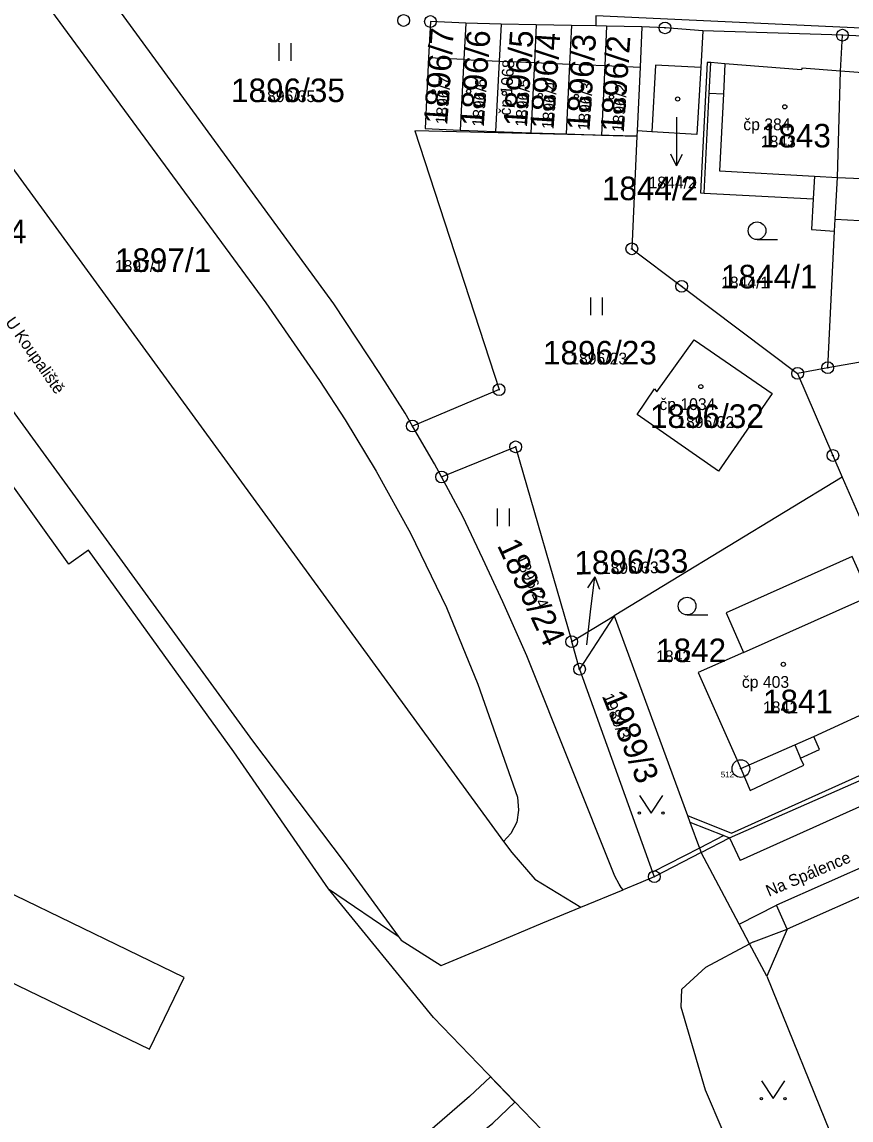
# Model space of a CAD drawing. Extents: x -763628 to -761565, y -976033 to -973833.
# Drawn here: x -762756 to -762685.6, y -975140.5 to -975047.2 of the extents above; entities that cross this region are included whole.
import ezdxf

# ---------------------------------------------------------------- set-up
doc = ezdxf.new("R2010")
doc.units = 0
for name, color, linetype in [('KN_cisla parcel 1000', 7, 'Continuous'), ('KN_cisla parcel 500', 7, 'Continuous'), ('KN_cisla parcel znacky', 7, 'Continuous'), ('KN_cisla popisna 500', 7, 'Continuous'), ('KN_hranice parcel', 7, 'Continuous'), ('KN_popisy', 7, 'Continuous'), ('KN_vecna bremena', 7, 'Continuous'), ('KN_vnitrni kresba parcel', 7, 'Continuous'), ('KN_znacky bodu BP', 7, 'Continuous'), ('KN_znacky budov', 7, 'Continuous'), ('KN_znacky kultur', 7, 'Continuous')]:
    doc.layers.add(name, color=color, linetype=linetype)

msp = doc.modelspace()

# ---------------------------------------------------------------- linework, layer by layer
at = {"layer": 'KN_cisla parcel znacky'}
for p, q in [((-762700.39, -975055.31), (-762700.39, -975056.44)), ((-762700.39, -975056.44), (-762700.39, -975059.441)), ((-762700.39, -975059.441), (-762700.891, -975058.44)), ((-762700.39, -975059.441), (-762699.889, -975058.44)), ((-762707.324, -975094.351), (-762707.943, -975095.284)), ((-762707.69, -975097.33), (-762707.324, -975094.351)), ((-762707.324, -975094.351), (-762706.949, -975095.406)), ((-762708.01, -975100.11), (-762707.69, -975097.33))]:
    msp.add_line(p, q, dxfattribs=at)
at = {"layer": 'KN_hranice parcel'}
for p, q in [((-762718.3, -975047.34), (-762721.3, -975047.19)), ((-762715.3, -975047.4), (-762718.3, -975047.34)), ((-762712.31, -975047.46), (-762715.3, -975047.4)), ((-762709.32, -975047.52), (-762712.31, -975047.46)), ((-762703.34, -975047.64), (-762706.33, -975047.58)), ((-762686.3, -975048.35), (-762698.17, -975047.99)), ((-762686.46, -975051.41), (-762686.3, -975048.35)), ((-762671.52, -975049.14), (-762686.3, -975048.35)), ((-762718.76, -975056.42), (-762715.76, -975056.53)), ((-762715.76, -975056.53), (-762712.76, -975056.63)), ((-762712.76, -975056.63), (-762709.77, -975056.73)), ((-762709.77, -975056.73), (-762706.77, -975056.83)), ((-762706.77, -975056.83), (-762703.77, -975056.93)), ((-762703.75, -975056.47), (-762703.77, -975056.93)), ((-762686.96, -975064.98), (-762686.91, -975063.97)), ((-762687.55, -975076.59), (-762686.96, -975064.98)), ((-762677.73, -975074.89), (-762687.55, -975076.59)), ((-762687.55, -975076.59), (-762690.11, -975077.07)), ((-762686.32, -975085.87), (-762705.69, -975097.65)), ((-762709.3, -975099.85), (-762705.69, -975097.65)), ((-762705.69, -975097.65), (-762708.63, -975102.19)), ((-762708.63, -975102.19), (-762709.3, -975099.85)), ((-762695.89, -975116.52), (-762680.64, -975109.8)), ((-762698.31, -975117.77), (-762695.89, -975116.52)), ((-762698.31, -975117.77), (-762702.28, -975119.81)), ((-762729.97, -975120.83), (-762724.03, -975124.87)), ((-762708.53, -975122.41), (-762704.94, -975120.92)), ((-762692.72, -975128.27), (-762694.19, -975125.51)), ((-762692.72, -975128.27), (-762682.21, -975154.12))]:
    msp.add_line(p, q, dxfattribs=at)
for points in [[(-762785.92, -975007.37), (-762783.32, -975009.09), (-762779.55, -975012.33), (-762777.34, -975014.46), (-762775.34, -975016.77), (-762773.46, -975019.17), (-762735.27, -975071.08), (-762730.71, -975077.67), (-762728.53, -975081.01), (-762725.91, -975085.36), (-762722.98, -975090.63), (-762719.94, -975096.96), (-762717.26, -975103.47), (-762713.9, -975113.06), (-762713.82, -975114.16), (-762713.96, -975115.19), (-762714.46, -975116.13), (-762715.09, -975116.82)], [(-762797.91, -975012), (-762794.68, -975013.3), (-762787.04, -975018.35), (-762781.09, -975024.71), (-762759.27, -975054.59), (-762760.08, -975055.18), (-762715.09, -975116.82)], [(-762722.83, -975081.54), (-762723.46, -975080.46), (-762725.61, -975077.07), (-762729.5, -975071.15), (-762747.33, -975046.79), (-762763.36, -975025.03)], [(-762721.3, -975047.19), (-762721.45, -975050.27), (-762721.76, -975056.27), (-762718.76, -975056.42)], [(-762718.3, -975047.34), (-762718.46, -975050.42), (-762718.76, -975056.42)], [(-762715.3, -975047.4), (-762715.46, -975050.55), (-762715.76, -975056.53)], [(-762712.31, -975047.46), (-762712.47, -975050.67), (-762712.76, -975056.63)], [(-762709.32, -975047.52), (-762709.48, -975050.8), (-762709.77, -975056.73)], [(-762706.33, -975047.58), (-762707.25, -975047.56), (-762709.32, -975047.52)], [(-762706.33, -975047.58), (-762706.48, -975050.93), (-762706.77, -975056.83)], [(-762703.34, -975047.64), (-762703.49, -975051.05), (-762703.75, -975056.47)], [(-762698.17, -975047.99), (-762698.33, -975051.08), (-762698.68, -975056.78), (-762702.48, -975056.55), (-762703.75, -975056.47)], [(-762698.17, -975047.99), (-762701.37, -975047.73), (-762703.34, -975047.64)], [(-762686.46, -975051.41), (-762689.76, -975051.16), (-762689.77, -975051.28), (-762696.28, -975050.78), (-762697.48, -975050.68), (-762697.78, -975050.66), (-762698.36, -975061.74), (-762698.05, -975061.75), (-762688.79, -975062.24), (-762688.94, -975064.85), (-762686.96, -975064.98)], [(-762686.91, -975063.97), (-762684.81, -975064.08), (-762677.65, -975064.49), (-762677.45, -975060.97), (-762677.12, -975055.27), (-762679.17, -975055.15), (-762679.24, -975052.09), (-762680.47, -975052), (-762683.08, -975051.79), (-762683.07, -975051.67), (-762686.46, -975051.41)], [(-762686.91, -975063.97), (-762686.72, -975060.44), (-762686.46, -975051.41)], [(-762703.77, -975056.93), (-762722.62, -975056.47), (-762715.47, -975078.45), (-762722.83, -975081.54)], [(-762703.77, -975056.93), (-762704.19, -975066.49), (-762699.96, -975069.67), (-762690.11, -975077.07)], [(-762785.36, -975080.34), (-762781.02, -975079.15), (-762780.06, -975078.83), (-762779.21, -975078.46), (-762777.09, -975077.31), (-762768.12, -975071.5), (-762767.24, -975071.02), (-762766.35, -975070.6), (-762765.4, -975070.23), (-762764.36, -975070.33), (-762763.53, -975070.99), (-762761.75, -975073.45), (-762736.42, -975108.28), (-762728.62, -975118.57), (-762724.03, -975124.87)], [(-762696.84, -975085.36), (-762703.74, -975080.56), (-762702.26, -975078.37), (-762702.07, -975078.63), (-762698.9, -975074.23), (-762692.27, -975078.78), (-762696.84, -975085.36)], [(-762729.97, -975120.83), (-762738.01, -975109.22), (-762750.35, -975092.09), (-762752.03, -975093.26), (-762764.14, -975076.37), (-762785.18, -975080.99)], [(-762690.11, -975077.07), (-762687.11, -975084.04), (-762686.32, -975085.87)], [(-762720.35, -975085.86), (-762720.94, -975084.76), (-762722.83, -975081.54)], [(-762720.35, -975085.86), (-762714.06, -975083.31), (-762709.3, -975099.85)], [(-762704.94, -975120.92), (-762705.11, -975120.74), (-762705.26, -975120.45), (-762705.63, -975119.76), (-762713.12, -975101.06), (-762715.15, -975096.47), (-762716.85, -975092.81), (-762718.55, -975089.21), (-762720.35, -975085.86)], [(-762686.32, -975085.87), (-762676.81, -975107.62), (-762676.63, -975108.03)], [(-762678.26, -975108.75), (-762678.44, -975108.34), (-762685.47, -975092.62), (-762696.19, -975097.41), (-762694.7, -975100.76), (-762698.55, -975102.48), (-762694.93, -975110.63), (-762694.15, -975112.48), (-762689.58, -975110.35), (-762689.85, -975109.74), (-762688.24, -975109.02), (-762688.74, -975107.9), (-762682.69, -975105.14), (-762680.82, -975109.39), (-762680.64, -975109.8)], [(-762705.69, -975097.65), (-762699.47, -975114.6), (-762699.26, -975115.17), (-762696.38, -975116.32), (-762695.89, -975116.52)], [(-762772.73, -975121.15), (-762745.16, -975134.45), (-762742.23, -975128.37), (-762799.67, -975100.53)], [(-762708.63, -975102.19), (-762702.43, -975119.44), (-762702.28, -975119.81)], [(-762661.4, -975111.16), (-762662.95, -975111.85), (-762666.1, -975113.23), (-762691, -975124.27), (-762692.72, -975128.27)], [(-762715.09, -975116.82), (-762714.38, -975117.75), (-762712.44, -975120.02), (-762708.53, -975122.41)], [(-762694.19, -975125.51), (-762695.07, -975123.85), (-762698.31, -975117.77)], [(-762702.28, -975119.81), (-762703.42, -975120.29), (-762704.94, -975120.92)], [(-762709.56, -975143.67), (-762721.05, -975131.78), (-762729.97, -975120.83)], [(-762724.03, -975124.87), (-762723.79, -975125.2), (-762720.4, -975127.34), (-762716.31, -975125.64), (-762711.75, -975123.74), (-762708.53, -975122.41)], [(-762672.04, -975157.56), (-762679.79, -975160.09), (-762681.71, -975160.35), (-762682.94, -975160.29), (-762684.09, -975159.87), (-762692.88, -975147), (-762696.44, -975141.44), (-762697.94, -975137.93), (-762699.99, -975130.89), (-762699.95, -975129.37), (-762697.89, -975127.49), (-762694.19, -975125.51)]]:
    msp.add_lwpolyline(points, dxfattribs=at)
at = {"layer": 'KN_vecna bremena'}
msp.add_lwpolyline([(-762752.49, -975168.34), (-762749.87, -975166.78), (-762744.73, -975164.31), (-762741.77, -975162.89), (-762736.76, -975158.71), (-762728.6, -975150.94), (-762716, -975140.74), (-762714.12, -975138.95), (-762716.2, -975136.8), (-762717.98, -975138.48), (-762727.04, -975146.33), (-762730.63, -975148.56), (-762735.96, -975153.74), (-762738.78, -975156.49), (-762746.55, -975162.98)], close=True, dxfattribs=at)
at = {"layer": 'KN_vnitrni kresba parcel'}
for p, q in [((-762641.14, -975049.74), (-762707.25, -975046.71)), ((-762707.25, -975046.71), (-762707.25, -975047.56)), ((-762718.46, -975050.42), (-762721.45, -975050.27)), ((-762718.46, -975050.42), (-762715.46, -975050.55)), ((-762715.46, -975050.55), (-762712.47, -975050.67)), ((-762712.47, -975050.67), (-762709.48, -975050.8)), ((-762709.48, -975050.8), (-762706.48, -975050.93)), ((-762697.63, -975053.27), (-762697.48, -975050.68)), ((-762696.28, -975050.78), (-762696.41, -975053.33)), ((-762706.48, -975050.93), (-762703.49, -975051.05)), ((-762702.18, -975050.89), (-762702.48, -975056.55)), ((-762698.33, -975051.08), (-762702.18, -975050.89)), ((-762698.05, -975061.75), (-762697.63, -975053.27)), ((-762697.63, -975053.27), (-762696.41, -975053.33)), ((-762696.41, -975053.33), (-762696.73, -975059.87)), ((-762696.73, -975059.87), (-762688.68, -975060.33)), ((-762688.68, -975060.33), (-762688.79, -975062.24)), ((-762688.68, -975060.33), (-762686.72, -975060.44)), ((-762686.72, -975060.44), (-762684.01, -975060.56)), ((-762591.8, -975077.98), (-762691.91, -975122.23)), ((-762623.28, -975086.29), (-762695, -975118.43)), ((-762694.7, -975100.76), (-762684.74, -975096.32)), ((-762694.93, -975110.63), (-762690.35, -975108.62)), ((-762690.35, -975108.62), (-762688.74, -975107.9)), ((-762690.35, -975108.62), (-762689.85, -975109.74)), ((-762695.72, -975116.1), (-762680.82, -975109.39)), ((-762699.47, -975114.6), (-762695.72, -975116.1)), ((-762699.26, -975115.17), (-762698.45, -975117.39)), ((-762696.38, -975116.32), (-762698.45, -975117.39)), ((-762695.89, -975116.52), (-762695, -975118.43)), ((-762698.45, -975117.39), (-762702.43, -975119.44)), ((-762698.45, -975117.39), (-762698.31, -975117.77)), ((-762695.07, -975123.85), (-762691.91, -975122.23)), ((-762691, -975124.27), (-762691.91, -975122.23)), ((-762693.85, -975125.33), (-762691, -975124.27)), ((-762693.85, -975125.33), (-762694.19, -975125.51))]:
    msp.add_line(p, q, dxfattribs=at)
at = {"layer": 'KN_znacky bodu BP'}
for centre, radius in [((-762723.58, -975047.1), 0.5), ((-762721.3, -975047.19), 0.5), ((-762701.37, -975047.73), 0.5), ((-762701.37, -975047.73), 0.0303), ((-762686.3, -975048.35), 0.5), ((-762686.3, -975048.35), 0.0303), ((-762704.19, -975066.49), 0.5), ((-762704.19, -975066.49), 0.0303), ((-762699.96, -975069.67), 0.5), ((-762699.96, -975069.67), 0.0303), ((-762690.11, -975077.07), 0.5), ((-762687.55, -975076.59), 0.5), ((-762687.55, -975076.59), 0.0303), ((-762690.11, -975077.07), 0.0303), ((-762715.47, -975078.45), 0.5), ((-762715.47, -975078.45), 0.0303), ((-762722.83, -975081.54), 0.5), ((-762722.83, -975081.54), 0.0303), ((-762714.06, -975083.31), 0.5), ((-762714.06, -975083.31), 0.0303), ((-762687.11, -975084.04), 0.5), ((-762687.11, -975084.04), 0.0303), ((-762720.35, -975085.86), 0.5), ((-762720.35, -975085.86), 0.0303), ((-762709.3, -975099.85), 0.5), ((-762709.3, -975099.85), 0.0303), ((-762708.63, -975102.19), 0.5), ((-762708.63, -975102.19), 0.0303), ((-762694.93, -975110.63), 0.75), ((-762694.93, -975110.63), 0.03), ((-762702.28, -975119.81), 0.5), ((-762702.28, -975119.81), 0.0303)]:
    msp.add_circle(centre, radius, dxfattribs=at)
at = {"layer": 'KN_znacky budov'}
for centre in [(-762721.057, -975053.159), (-762718.047, -975053.119), (-762715.017, -975053.289), (-762711.967, -975053.449), (-762708.897, -975053.549), (-762705.917, -975053.599), (-762700.297, -975053.769), (-762691.197, -975054.429), (-762698.327, -975078.189), (-762691.317, -975101.779)]:
    msp.add_circle(centre, 0.175, dxfattribs=at)
at = {"layer": 'KN_znacky kultur'}
for p, q in [((-762734.141, -975050.53), (-762734.141, -975049.03)), ((-762733.14, -975050.53), (-762733.14, -975049.03)), ((-762693.553, -975065.7), (-762691.803, -975065.7)), ((-762707.671, -975072.13), (-762707.671, -975070.63)), ((-762706.67, -975072.13), (-762706.67, -975070.63)), ((-762715.591, -975090.05), (-762715.591, -975088.55)), ((-762714.59, -975090.05), (-762714.59, -975088.55)), ((-762699.493, -975097.58), (-762697.743, -975097.58))]:
    msp.add_line(p, q, dxfattribs=at)
for points in [[(-762703.55, -975112.909), (-762702.55, -975114.41), (-762701.55, -975112.909)], [(-762693.18, -975137.149), (-762692.18, -975138.65), (-762691.18, -975137.149)]]:
    msp.add_lwpolyline(points, dxfattribs=at)
for centre, radius in [((-762693.553, -975064.95), 0.75), ((-762699.493, -975096.83), 0.75), ((-762703.55, -975114.409), 0.1), ((-762701.55, -975114.409), 0.1), ((-762693.18, -975138.649), 0.1), ((-762691.18, -975138.649), 0.1)]:
    msp.add_circle(centre, radius, dxfattribs=at)

# ---------------------------------------------------------------- texts
at = {"layer": 'KN_cisla parcel 1000'}
for s, rotation, p in [('1896/7', 86, (-762719.873, -975055.955)), ('1896/6', 86, (-762716.772, -975056.15)), ('1896/5', 86, (-762713.103, -975056.159)), ('1896/4', 86, (-762710.84, -975056.365)), ('1896/3', 86, (-762707.787, -975056.475)), ('1896/2', 86, (-762704.877, -975056.618)), ('1896/24', 295, (-762715.664, -975091.666)), ('1896/33', 1, (-762709.05, -975094.159)), ('1989/3', 292, (-762706.742, -975104.481))]:
    msp.add_text(s, height=2, rotation=rotation, dxfattribs=at).set_placement(p)
for s, p in [('1896/35', (-762738.235, -975054.03)), ('1843', (-762693.23, -975057.88)), ('1844/2', (-762706.736, -975062.36)), ('1897/4', (-762763.8, -975066.02)), ('1897/1', (-762748.11, -975068.45)), ('1844/1', (-762696.61, -975069.85)), ('1896/23', (-762711.738, -975076.31)), ('1896/32', (-762702.648, -975081.7)), ('1842', (-762702.13, -975101.59)), ('1841', (-762693.05, -975105.93))]:
    msp.add_text(s, height=2, dxfattribs=at).set_placement(p)
at = {"layer": 'KN_cisla parcel 500'}
for s, rotation, p in [('1896/7', 86, (-762719.873, -975055.955)), ('1896/6', 86, (-762716.772, -975056.15)), ('1896/5', 86, (-762713.103, -975056.159)), ('1896/4', 86, (-762710.84, -975056.365)), ('1896/3', 86, (-762707.787, -975056.475)), ('1896/2', 86, (-762704.877, -975056.618)), ('1896/24', 295, (-762714.153, -975092.764)), ('1896/33', 1, (-762706.734, -975094.119)), ('1989/3', 292, (-762706.742, -975104.481))]:
    msp.add_text(s, height=1, rotation=rotation, dxfattribs=at).set_placement(p)
for s, p in [('1896/35', (-762735.918, -975054.03)), ('1843', (-762693.23, -975057.88)), ('1844/2', (-762702.769, -975061.36)), ('1897/1', (-762748.11, -975068.45)), ('1844/1', (-762696.61, -975069.85)), ('1896/23', (-762709.422, -975076.31)), ('1896/32', (-762700.332, -975081.7)), ('1842', (-762702.13, -975101.59)), ('1841', (-762693.05, -975105.93))]:
    msp.add_text(s, height=1, dxfattribs=at).set_placement(p)
at = {"layer": 'KN_cisla popisna 500'}
msp.add_text('čp 1068', height=1, rotation=86, dxfattribs=at).set_placement((-762714.491, -975055.201))
for s, p in [('čp 384', (-762694.721, -975056.421)), ('čp 1034', (-762701.851, -975080.181)), ('čp 403', (-762694.841, -975103.771))]:
    msp.add_text(s, height=1, dxfattribs=at).set_placement(p)
at = {"layer": 'KN_popisy'}
for s, rotation, p in [('U Koupaliště', 305, (-762757.456, -975072.717)), ('Na Spálence', 23, (-762692.545, -975121.529))]:
    msp.add_text(s, height=1, rotation=rotation, dxfattribs=at).set_placement(p)
at = {"layer": 'KN_znacky bodu BP'}
msp.add_text('512', height=0.5, dxfattribs=at).set_placement((-762696.629, -975111.38))

doc.saveas('drawing.dxf')
